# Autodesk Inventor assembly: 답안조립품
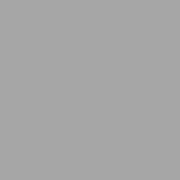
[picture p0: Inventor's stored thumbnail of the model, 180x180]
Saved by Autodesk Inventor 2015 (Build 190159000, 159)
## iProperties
Created: 2016-02
Part Number: 답안조립품
Document SubType Name: Assembly
Designer: Administrator
Author: Administrator
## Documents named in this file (1)
- C:\Users\Administrator\Desktop\460219V1007\답안조립품.iam
